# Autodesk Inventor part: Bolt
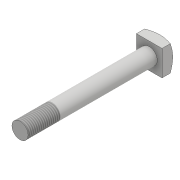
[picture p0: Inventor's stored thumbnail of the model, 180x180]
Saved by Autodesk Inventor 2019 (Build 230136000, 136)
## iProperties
Created: 2016-05
Part Number: Bolt
Material: Generic
Document SubType Name: Modeling
Designer: CADCIM
Density: 1 g/cm^3
Appearance: Default
Author: CADCIM
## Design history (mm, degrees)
sketch "Sketch1"
  geometry: L1 (9.5, 9.5)-(-9.5, 9.5); L2 (-9.5, 9.5)-(-9.5, -9.5); L3 (-9.5, -9.5)-(9.5, -9.5); L4 (9.5, -9.5)-(9.5, 9.5); L5 (0, 0)-(0, 14.108); L6 (0, 0)-(-17.802, 0)
  constraints: 12 end point, 2 horizontal, 2 parallel, 2 perpendicular, 1 vertical, 2 other
  dimensions: "d0" = 19 distance of L3.end L1.start
extrude "Extrusion1" new body sketch "Sketch1" distance "d1" = 8; taper "d2" = 0 deg
sketch "Sketch3"
  geometry: L1 (9.5, 9.5)-(-9.5, 9.5) reference; C1 r 9.5 at (0, 0); 1 further point
  constraints: 1 centre point, 1 coincident, 1 tangent
extrude "Extrusion3" sketch "Sketch3" distance "d6" = 96; taper "d7" = 65 deg
sketch "Sketch4"
  geometry: C1 r 6 at (0, 0); 1 further point
  constraints: 1 centre point, 1 coincident
  dimensions: "d10" = 12 diameter of C1
extrude "Extrusion4" join sketch "Sketch4" distance "d11" = 96; taper "d12" = 0 deg
thread "Thread2" dims "d13" = 24, "d14" = 0
body "Solid1"
